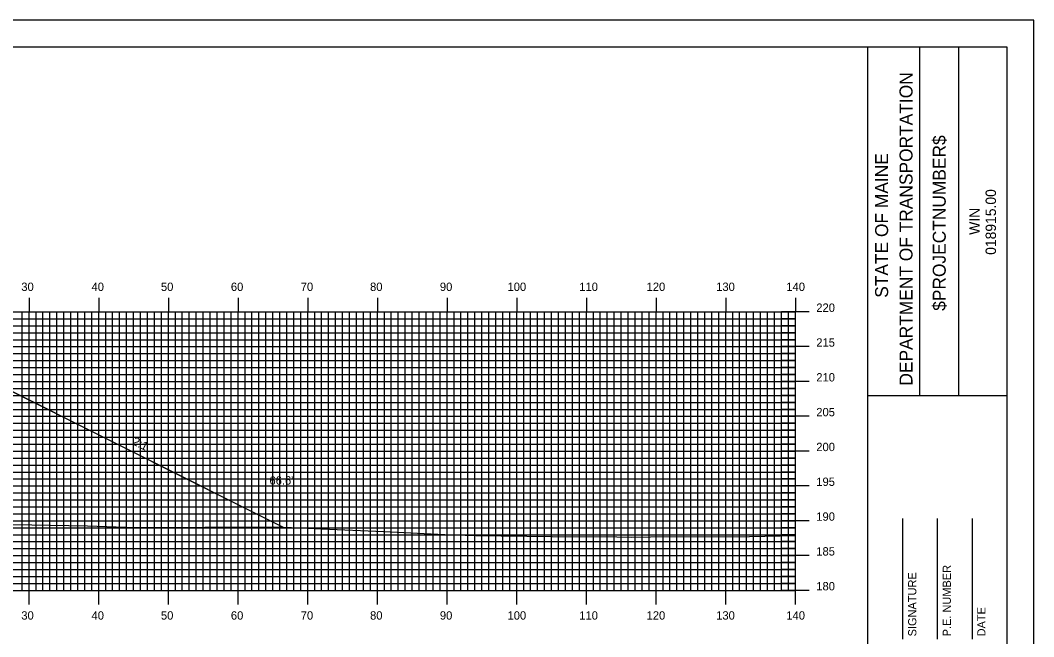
# Model space of a CAD drawing. Extents: x 1810587 to 1810930, y 442591 to 442811.
# Drawn here: x 1810781.1 to 1810926.6, y 442722 to 442810.5 of the extents above; entities that cross this region are included whole.
import ezdxf

# ---------------------------------------------------------------- set-up
doc = ezdxf.new("R2010")
doc.units = 0
for name, color, linetype in [('ANNOTATION', 7, 'Continuous'), ('BORDER', 7, 'Continuous'), ('D_Roadway_Centerline', 7, 'Continuous'), ('D_Roadway_SlopeLines', 7, 'Continuous'), ('D_Text_Standard', 7, 'Continuous'), ('H_V ANNOTATION', 7, 'Continuous'), ('MAJOR', 7, 'Continuous'), ('MINOR', 7, 'Continuous'), ('PLOT BOUNDARY', 7, 'Continuous'), ('S_Roadway_Centerline', 7, 'Continuous')]:
    doc.layers.add(name, color=color, linetype=linetype)

msp = doc.modelspace()

# ---------------------------------------------------------------- linework, layer by layer
at = {"layer": 'BORDER'}
for p, q in [((1810902.78, 442596.67), (1810902.78, 442806.67)), ((1810910.23, 442756.66), (1810910.23, 442806.66)), ((1810915.82, 442756.66), (1810915.82, 442806.66)), ((1810902.78, 442756.65), (1810922.78, 442756.65)), ((1810907.78, 442721.67), (1810907.78, 442738.97)), ((1810912.78, 442721.67), (1810912.78, 442738.97)), ((1810917.78, 442721.67), (1810917.78, 442738.97))]:
    msp.add_line(p, q, dxfattribs=at)
msp.add_lwpolyline([(1810602.78, 442596.67), (1810922.78, 442596.67), (1810922.78, 442806.67), (1810602.78, 442806.67)], close=True, dxfattribs=at)
at = {"layer": 'D_Roadway_Centerline'}
msp.add_lwpolyline([(1810685.57, 442739.07), (1810724.17, 442758.37), (1810729.38, 442760.98), (1810732.38, 442761.04), (1810740.38, 442761.2), (1810752.38, 442760.62), (1810764.38, 442760.04), (1810772.38, 442759.66), (1810775.38, 442759.52), (1810780.91, 442756.75), (1810818.96, 442737.72)], dxfattribs=at)
at = {"layer": 'D_Roadway_SlopeLines'}
msp.add_lwpolyline([(1810775.38, 442759.52), (1810818.96, 442737.72)], dxfattribs=at)
at = {"layer": 'MAJOR'}
for p, q in [((1810782.38, 442770.67), (1810782.38, 442768.67)), ((1810792.38, 442770.67), (1810792.38, 442768.67)), ((1810802.38, 442770.67), (1810802.38, 442768.67)), ((1810812.38, 442770.67), (1810812.38, 442768.67)), ((1810822.38, 442770.67), (1810822.38, 442768.67)), ((1810832.38, 442770.67), (1810832.38, 442768.67)), ((1810842.38, 442770.67), (1810842.38, 442768.67)), ((1810852.38, 442770.67), (1810852.38, 442768.67)), ((1810862.38, 442770.67), (1810862.38, 442768.67)), ((1810872.38, 442770.67), (1810872.38, 442768.67)), ((1810882.38, 442770.67), (1810882.38, 442768.67)), ((1810892.38, 442770.67), (1810892.38, 442768.67)), ((1810612.38, 442768.67), (1810892.38, 442768.67)), ((1810612.38, 442768.67), (1810892.38, 442768.67)), ((1810782.38, 442728.67), (1810782.38, 442768.67)), ((1810792.38, 442728.67), (1810792.38, 442768.67)), ((1810802.38, 442728.67), (1810802.38, 442768.67)), ((1810812.38, 442728.67), (1810812.38, 442768.67)), ((1810822.38, 442728.67), (1810822.38, 442768.67)), ((1810832.38, 442728.67), (1810832.38, 442768.67)), ((1810842.38, 442728.67), (1810842.38, 442768.67)), ((1810852.38, 442728.67), (1810852.38, 442768.67)), ((1810862.38, 442728.67), (1810862.38, 442768.67)), ((1810872.38, 442728.67), (1810872.38, 442768.67)), ((1810882.38, 442728.67), (1810882.38, 442768.67)), ((1810894.38, 442768.67), (1810890.37, 442768.67)), ((1810892.38, 442728.67), (1810892.38, 442768.67)), ((1810892.38, 442728.67), (1810892.38, 442768.67)), ((1810612.38, 442763.67), (1810892.38, 442763.67)), ((1810894.38, 442763.67), (1810890.37, 442763.67)), ((1810612.38, 442758.67), (1810892.38, 442758.67)), ((1810894.38, 442758.67), (1810890.37, 442758.67)), ((1810612.38, 442753.67), (1810892.38, 442753.67)), ((1810894.38, 442753.67), (1810890.37, 442753.67)), ((1810612.38, 442748.67), (1810892.38, 442748.67)), ((1810894.38, 442748.67), (1810890.37, 442748.67)), ((1810612.38, 442743.67), (1810892.38, 442743.67)), ((1810894.38, 442743.67), (1810890.37, 442743.67)), ((1810612.38, 442738.67), (1810892.38, 442738.67)), ((1810894.38, 442738.67), (1810890.37, 442738.67)), ((1810612.38, 442733.67), (1810892.38, 442733.67)), ((1810894.38, 442733.67), (1810890.37, 442733.67)), ((1810612.38, 442728.67), (1810892.38, 442728.67)), ((1810612.38, 442728.67), (1810892.38, 442728.67)), ((1810782.38, 442726.66), (1810782.38, 442728.67)), ((1810792.38, 442726.66), (1810792.38, 442728.67)), ((1810802.38, 442726.66), (1810802.38, 442728.67)), ((1810812.38, 442726.66), (1810812.38, 442728.67)), ((1810822.38, 442726.66), (1810822.38, 442728.67)), ((1810832.38, 442726.66), (1810832.38, 442728.67)), ((1810842.38, 442726.66), (1810842.38, 442728.67)), ((1810852.38, 442726.66), (1810852.38, 442728.67)), ((1810862.38, 442726.66), (1810862.38, 442728.67)), ((1810872.38, 442726.66), (1810872.38, 442728.67)), ((1810882.38, 442726.66), (1810882.38, 442728.67)), ((1810894.38, 442728.67), (1810890.37, 442728.67)), ((1810892.38, 442726.66), (1810892.38, 442728.67))]:
    msp.add_line(p, q, dxfattribs=at)
at = {"layer": 'MINOR'}
for p, q in [((1810781.38, 442728.67), (1810781.38, 442768.67)), ((1810783.38, 442728.67), (1810783.38, 442768.67)), ((1810784.38, 442728.67), (1810784.38, 442768.67)), ((1810785.38, 442728.67), (1810785.38, 442768.67)), ((1810786.38, 442728.67), (1810786.38, 442768.67)), ((1810787.38, 442728.67), (1810787.38, 442768.67)), ((1810788.38, 442728.67), (1810788.38, 442768.67)), ((1810789.38, 442728.67), (1810789.38, 442768.67)), ((1810790.38, 442728.67), (1810790.38, 442768.67)), ((1810791.38, 442728.67), (1810791.38, 442768.67)), ((1810793.38, 442728.67), (1810793.38, 442768.67)), ((1810794.38, 442728.67), (1810794.38, 442768.67)), ((1810795.38, 442728.67), (1810795.38, 442768.67)), ((1810796.38, 442728.67), (1810796.38, 442768.67)), ((1810797.38, 442728.67), (1810797.38, 442768.67)), ((1810798.38, 442728.67), (1810798.38, 442768.67)), ((1810799.38, 442728.67), (1810799.38, 442768.67)), ((1810800.38, 442728.67), (1810800.38, 442768.67)), ((1810801.38, 442728.67), (1810801.38, 442768.67)), ((1810803.38, 442728.67), (1810803.38, 442768.67)), ((1810804.38, 442728.67), (1810804.38, 442768.67)), ((1810805.38, 442728.67), (1810805.38, 442768.67)), ((1810806.38, 442728.67), (1810806.38, 442768.67)), ((1810807.38, 442728.67), (1810807.38, 442768.67)), ((1810808.38, 442728.67), (1810808.38, 442768.67)), ((1810809.38, 442728.67), (1810809.38, 442768.67)), ((1810810.38, 442728.67), (1810810.38, 442768.67)), ((1810811.38, 442728.67), (1810811.38, 442768.67)), ((1810813.38, 442728.67), (1810813.38, 442768.67)), ((1810814.38, 442728.67), (1810814.38, 442768.67)), ((1810815.38, 442728.67), (1810815.38, 442768.67)), ((1810816.38, 442728.67), (1810816.38, 442768.67)), ((1810817.38, 442728.67), (1810817.38, 442768.67)), ((1810818.38, 442728.67), (1810818.38, 442768.67)), ((1810819.38, 442728.67), (1810819.38, 442768.67)), ((1810820.38, 442728.67), (1810820.38, 442768.67)), ((1810821.38, 442728.67), (1810821.38, 442768.67)), ((1810823.38, 442728.67), (1810823.38, 442768.67)), ((1810824.38, 442728.67), (1810824.38, 442768.67)), ((1810825.38, 442728.67), (1810825.38, 442768.67)), ((1810826.38, 442728.67), (1810826.38, 442768.67)), ((1810827.38, 442728.67), (1810827.38, 442768.67)), ((1810828.38, 442728.67), (1810828.38, 442768.67)), ((1810829.38, 442728.67), (1810829.38, 442768.67)), ((1810830.38, 442728.67), (1810830.38, 442768.67)), ((1810831.38, 442728.67), (1810831.38, 442768.67)), ((1810833.38, 442728.67), (1810833.38, 442768.67)), ((1810834.38, 442728.67), (1810834.38, 442768.67)), ((1810835.38, 442728.67), (1810835.38, 442768.67)), ((1810836.38, 442728.67), (1810836.38, 442768.67)), ((1810837.38, 442728.67), (1810837.38, 442768.67)), ((1810838.38, 442728.67), (1810838.38, 442768.67)), ((1810839.38, 442728.67), (1810839.38, 442768.67)), ((1810840.38, 442728.67), (1810840.38, 442768.67)), ((1810841.38, 442728.67), (1810841.38, 442768.67)), ((1810843.38, 442728.67), (1810843.38, 442768.67)), ((1810844.38, 442728.67), (1810844.38, 442768.67)), ((1810845.38, 442728.67), (1810845.38, 442768.67)), ((1810846.38, 442728.67), (1810846.38, 442768.67)), ((1810847.38, 442728.67), (1810847.38, 442768.67)), ((1810848.38, 442728.67), (1810848.38, 442768.67)), ((1810849.38, 442728.67), (1810849.38, 442768.67)), ((1810850.38, 442728.67), (1810850.38, 442768.67)), ((1810851.38, 442728.67), (1810851.38, 442768.67)), ((1810853.38, 442728.67), (1810853.38, 442768.67)), ((1810854.38, 442728.67), (1810854.38, 442768.67)), ((1810855.38, 442728.67), (1810855.38, 442768.67)), ((1810856.38, 442728.67), (1810856.38, 442768.67)), ((1810857.38, 442728.67), (1810857.38, 442768.67)), ((1810858.38, 442728.67), (1810858.38, 442768.67)), ((1810859.38, 442728.67), (1810859.38, 442768.67)), ((1810860.38, 442728.67), (1810860.38, 442768.67)), ((1810861.38, 442728.67), (1810861.38, 442768.67)), ((1810863.38, 442728.67), (1810863.38, 442768.67)), ((1810864.38, 442728.67), (1810864.38, 442768.67)), ((1810865.38, 442728.67), (1810865.38, 442768.67)), ((1810866.38, 442728.67), (1810866.38, 442768.67)), ((1810867.38, 442728.67), (1810867.38, 442768.67)), ((1810868.38, 442728.67), (1810868.38, 442768.67)), ((1810869.38, 442728.67), (1810869.38, 442768.67)), ((1810870.38, 442728.67), (1810870.38, 442768.67)), ((1810871.38, 442728.67), (1810871.38, 442768.67)), ((1810873.38, 442728.67), (1810873.38, 442768.67)), ((1810874.38, 442728.67), (1810874.38, 442768.67)), ((1810875.38, 442728.67), (1810875.38, 442768.67)), ((1810876.38, 442728.67), (1810876.38, 442768.67)), ((1810877.38, 442728.67), (1810877.38, 442768.67)), ((1810878.38, 442728.67), (1810878.38, 442768.67)), ((1810879.38, 442728.67), (1810879.38, 442768.67)), ((1810880.38, 442728.67), (1810880.38, 442768.67)), ((1810881.38, 442728.67), (1810881.38, 442768.67)), ((1810883.38, 442728.67), (1810883.38, 442768.67)), ((1810884.38, 442728.67), (1810884.38, 442768.67)), ((1810885.38, 442728.67), (1810885.38, 442768.67)), ((1810886.38, 442728.67), (1810886.38, 442768.67)), ((1810887.38, 442728.67), (1810887.38, 442768.67)), ((1810888.38, 442728.67), (1810888.38, 442768.67)), ((1810889.38, 442728.67), (1810889.38, 442768.67)), ((1810890.38, 442728.67), (1810890.38, 442768.67)), ((1810891.38, 442728.67), (1810891.38, 442768.67)), ((1810612.38, 442767.67), (1810892.38, 442767.67)), ((1810892.38, 442767.67), (1810890.37, 442767.67)), ((1810612.38, 442766.67), (1810892.38, 442766.67)), ((1810612.38, 442765.67), (1810892.38, 442765.67)), ((1810892.38, 442766.67), (1810890.37, 442766.67)), ((1810892.38, 442765.67), (1810890.37, 442765.67)), ((1810612.38, 442764.67), (1810892.38, 442764.67)), ((1810892.38, 442764.67), (1810890.37, 442764.67)), ((1810612.38, 442762.67), (1810892.38, 442762.67)), ((1810892.38, 442762.67), (1810890.37, 442762.67)), ((1810612.38, 442761.67), (1810892.38, 442761.67)), ((1810892.38, 442761.67), (1810890.37, 442761.67)), ((1810612.38, 442760.67), (1810892.38, 442760.67)), ((1810892.38, 442760.67), (1810890.37, 442760.67)), ((1810612.38, 442759.67), (1810892.38, 442759.67)), ((1810892.38, 442759.67), (1810890.37, 442759.67)), ((1810612.38, 442757.67), (1810892.38, 442757.67)), ((1810892.38, 442757.67), (1810890.37, 442757.67)), ((1810612.38, 442756.67), (1810892.38, 442756.67)), ((1810612.38, 442755.67), (1810892.38, 442755.67)), ((1810892.38, 442756.67), (1810890.37, 442756.67)), ((1810892.38, 442755.67), (1810890.37, 442755.67)), ((1810612.38, 442754.67), (1810892.38, 442754.67)), ((1810892.38, 442754.67), (1810890.37, 442754.67)), ((1810612.38, 442752.67), (1810892.38, 442752.67)), ((1810892.38, 442752.67), (1810890.37, 442752.67)), ((1810612.38, 442751.67), (1810892.38, 442751.67)), ((1810892.38, 442751.67), (1810890.37, 442751.67)), ((1810612.38, 442750.67), (1810892.38, 442750.67)), ((1810612.38, 442749.67), (1810892.38, 442749.67)), ((1810892.38, 442750.67), (1810890.37, 442750.67)), ((1810892.38, 442749.67), (1810890.37, 442749.67)), ((1810612.38, 442747.67), (1810892.38, 442747.67)), ((1810612.38, 442746.67), (1810892.38, 442746.67)), ((1810892.38, 442747.67), (1810890.37, 442747.67)), ((1810892.38, 442746.67), (1810890.37, 442746.67)), ((1810612.38, 442745.67), (1810892.38, 442745.67)), ((1810892.38, 442745.67), (1810890.37, 442745.67)), ((1810612.38, 442744.67), (1810892.38, 442744.67)), ((1810892.38, 442744.67), (1810890.37, 442744.67)), ((1810612.38, 442742.67), (1810892.38, 442742.67)), ((1810892.38, 442742.67), (1810890.37, 442742.67)), ((1810612.38, 442741.67), (1810892.38, 442741.67)), ((1810892.38, 442741.67), (1810890.37, 442741.67)), ((1810612.38, 442740.67), (1810892.38, 442740.67)), ((1810612.38, 442739.67), (1810892.38, 442739.67)), ((1810892.38, 442740.67), (1810890.37, 442740.67)), ((1810892.38, 442739.67), (1810890.37, 442739.67)), ((1810612.38, 442737.67), (1810892.38, 442737.67)), ((1810612.38, 442736.67), (1810892.38, 442736.67)), ((1810892.38, 442737.67), (1810890.37, 442737.67)), ((1810892.38, 442736.67), (1810890.37, 442736.67)), ((1810612.38, 442735.67), (1810892.38, 442735.67)), ((1810892.38, 442735.67), (1810890.37, 442735.67)), ((1810612.38, 442734.67), (1810892.38, 442734.67)), ((1810892.38, 442734.67), (1810890.37, 442734.67)), ((1810612.38, 442732.67), (1810892.38, 442732.67)), ((1810892.38, 442732.67), (1810890.37, 442732.67)), ((1810612.38, 442731.67), (1810892.38, 442731.67)), ((1810612.38, 442730.67), (1810892.38, 442730.67)), ((1810892.38, 442731.67), (1810890.37, 442731.67)), ((1810892.38, 442730.67), (1810890.37, 442730.67)), ((1810612.38, 442729.67), (1810892.38, 442729.67)), ((1810892.38, 442729.67), (1810890.37, 442729.67))]:
    msp.add_line(p, q, dxfattribs=at)
at = {"layer": 'PLOT BOUNDARY'}
msp.add_lwpolyline([(1810586.59, 442590.55), (1810926.59, 442590.55), (1810926.59, 442810.55), (1810586.59, 442810.55)], close=True, dxfattribs=at)
at = {"layer": 'S_Roadway_Centerline'}
msp.add_lwpolyline([(1810764.36, 442738.19), (1810782.79, 442738.08), (1810790.79, 442737.92), (1810797.65, 442737.72), (1810817.5, 442737.78), (1810821.36, 442737.64), (1810824.43, 442737.51), (1810833.25, 442737.12), (1810843, 442736.63), (1810845, 442736.58), (1810846.53, 442736.53), (1810857.47, 442736.41), (1810866.74, 442736.34), (1810868.88, 442736.33), (1810871.56, 442736.34), (1810885.81, 442736.43), (1810892.38, 442736.54)], dxfattribs=at)

# ---------------------------------------------------------------- texts
at = {"layer": 'ANNOTATION'}
msp.add_text('2:1', height=1.2, rotation=333.4349, dxfattribs=at).set_placement((1810797.1, 442749.69))
at = {"layer": 'BORDER'}
for s, height, p in [('DEPARTMENT OF TRANSPORTATION', 1.8635, (1810909.19, 442758.08)), ('$PROJECTNUMBER$', 1.8635, (1810913.96, 442768.82)), ('STATE OF MAINE', 1.8635, (1810905.69, 442770.69)), ('018915.00', 1.491, (1810921.17, 442776.86)), ('WIN', 1.491, (1810918.85, 442779.73)), ('P.E. NUMBER', 1.1811, (1810914.7, 442722.06)), ('SIGNATURE', 1.181, (1810909.74, 442722.06)), ('DATE', 1.181, (1810919.66, 442722.06))]:
    msp.add_text(s, height=height, rotation=90, dxfattribs=at).set_placement(p)
at = {"layer": 'D_Text_Standard'}
msp.add_text("66.6'", height=1.2, dxfattribs=at).set_placement((1810816.89, 442743.86))
at = {"layer": 'H_V ANNOTATION'}
for s, p in [('30', (1810781.27, 442771.67)), ('40', (1810791.35, 442771.67)), ('50', (1810801.31, 442771.67)), ('60', (1810811.35, 442771.67)), ('70', (1810821.38, 442771.67)), ('80', (1810831.33, 442771.67)), ('90', (1810841.35, 442771.67)), ('100', (1810851.06, 442771.67)), ('110', (1810861.36, 442771.67)), ('120', (1810871.02, 442771.67)), ('130', (1810881.01, 442771.67)), ('140', (1810891.08, 442771.67)), ('220', (1810895.38, 442768.67)), ('215', (1810895.38, 442763.67)), ('210', (1810895.38, 442758.67)), ('205', (1810895.38, 442753.67)), ('200', (1810895.38, 442748.67)), ('195', (1810895.38, 442743.67)), ('190', (1810895.38, 442738.67)), ('185', (1810895.38, 442733.67)), ('180', (1810895.38, 442728.67)), ('30', (1810781.27, 442724.47)), ('40', (1810791.35, 442724.47)), ('50', (1810801.31, 442724.47)), ('60', (1810811.35, 442724.47)), ('70', (1810821.38, 442724.47)), ('80', (1810831.33, 442724.47)), ('90', (1810841.35, 442724.47)), ('100', (1810851.06, 442724.47)), ('110', (1810861.36, 442724.47)), ('120', (1810871.02, 442724.47)), ('130', (1810881.01, 442724.47)), ('140', (1810891.08, 442724.47))]:
    msp.add_text(s, height=1.2, dxfattribs=at).set_placement(p)

doc.saveas('drawing.dxf')
